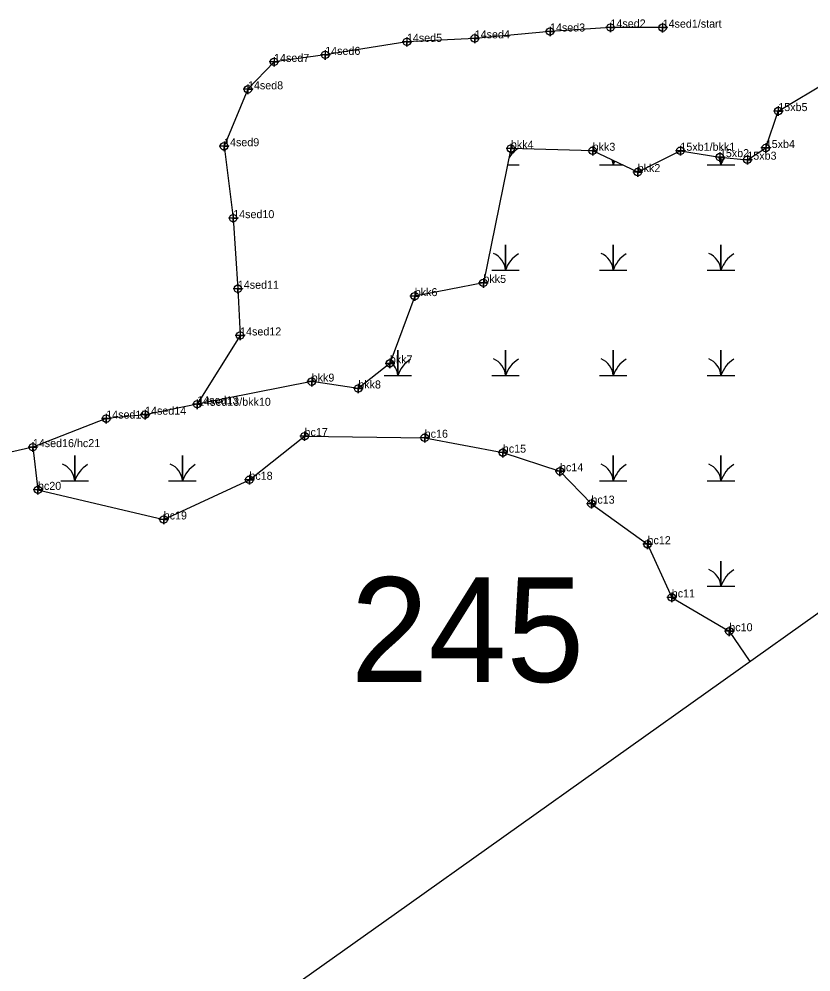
# Model space of a CAD drawing. Extents: x 2071991 to 2268989, y 436479 to 469629.
# Drawn here: x 2266266 to 2266760, y 442376 to 442971 of the extents above; entities that cross this region are included whole.
import ezdxf

# ---------------------------------------------------------------- set-up
doc = ezdxf.new("R2010")
doc.units = 0
for name, color, linetype in [('approx_PSA', 7, 'Continuous'), ('Default', 7, 'Continuous'), ('Exist Environmental Wetland Boundary', 7, 'Continuous'), ('Exist Environmental Wetland Boundary Cogo Comment', 7, 'Continuous'), ('Exist Environmental Wetland Boundary Cogo Point CELL', 7, 'Continuous'), ('Exist Hydro Jurisdictional Stream or Body of Water NEU Mitigable Cogo Comment', 7, 'Continuous'), ('Exist Hydro Jurisdictional Stream or Body of Water NEU Mitigable Cogo Point CELL', 7, 'Continuous'), ('Exist Hydro Jurisdictional Stream or Body of Water NEU NonMitigable', 7, 'Continuous'), ('Exist Hydro Jurisdictional Stream or Body of Water NEU NonMitigable Cogo Comment', 7, 'Continuous'), ('Exist Hydro Jurisdictional Stream or Body of Water NEU NonMitigable Cogo Point CELL', 7, 'Continuous'), ('Exist Hydro Swamp or Marsh', 7, 'Continuous')]:
    doc.layers.add(name, color=color, linetype=linetype)

msp = doc.modelspace()

# ---------------------------------------------------------------- linework, layer by layer
at = {"layer": 'approx_PSA'}
for p, q in [((2267016.7, 442780.01), (2266499.86, 442411.99)), ((2266499.86, 442411.99), (2265822.87, 441931.57))]:
    msp.add_line(p, q, dxfattribs=at)
at = {"layer": 'Exist Environmental Wetland Boundary'}
for points in [[(2266678.5, 442889.05), (2266703.12, 442885.09), (2266720.26, 442883.46), (2266731.75, 442890.78), (2266739.57, 442913.82), (2266772.08, 442933.43)], [(2266678.5, 442889.05), (2266651.85, 442875.73), (2266623.75, 442889.04), (2266572.7, 442890.43), (2266555.58, 442806.57), (2266512.75, 442798.29), (2266497.2, 442756.32), (2266477.5, 442740.62), (2266448.44, 442744.91), (2266377.04, 442730.81)], [(2266274.43, 442704.01), (2266277.64, 442677.33), (2266356.08, 442658.85), (2266409.55, 442683.62), (2266443.97, 442710.87), (2266518.94, 442709.86), (2266567.7, 442700.56), (2266603.36, 442688.91), (2266622.96, 442668.7), (2266657.98, 442643.38), (2266673.11, 442610.19), (2266709.02, 442589.04), (2266721.86, 442570.07)]]:
    msp.add_lwpolyline(points, dxfattribs=at)
at = {"layer": 'Exist Environmental Wetland Boundary Cogo Point CELL'}
for points in [[(2266739.57, 442916.82), (2266739.57, 442910.82), (2266739.57, 442913.82), (2266742.57, 442913.82), (2266736.57, 442913.82)], [(2266572.7, 442893.43), (2266572.7, 442887.43), (2266572.7, 442890.43), (2266575.7, 442890.43), (2266569.7, 442890.43)], [(2266623.75, 442892.04), (2266623.75, 442886.04), (2266623.75, 442889.04), (2266626.75, 442889.04), (2266620.75, 442889.04)], [(2266678.5, 442892.05), (2266678.5, 442886.05), (2266678.5, 442889.05), (2266681.5, 442889.05), (2266675.5, 442889.05)], [(2266731.75, 442893.78), (2266731.75, 442887.78), (2266731.75, 442890.78), (2266734.75, 442890.78), (2266728.75, 442890.78)], [(2266703.12, 442888.09), (2266703.12, 442882.09), (2266703.12, 442885.09), (2266706.12, 442885.09), (2266700.12, 442885.09)], [(2266720.26, 442886.46), (2266720.26, 442880.46), (2266720.26, 442883.46), (2266723.26, 442883.46), (2266717.26, 442883.46)], [(2266651.85, 442878.73), (2266651.85, 442872.73), (2266651.85, 442875.73), (2266654.85, 442875.73), (2266648.85, 442875.73)], [(2266555.58, 442809.57), (2266555.58, 442803.57), (2266555.58, 442806.57), (2266558.58, 442806.57), (2266552.58, 442806.57)], [(2266512.75, 442801.29), (2266512.75, 442795.29), (2266512.75, 442798.29), (2266515.75, 442798.29), (2266509.75, 442798.29)], [(2266497.2, 442759.32), (2266497.2, 442753.32), (2266497.2, 442756.32), (2266500.2, 442756.32), (2266494.2, 442756.32)], [(2266448.44, 442747.91), (2266448.44, 442741.91), (2266448.44, 442744.91), (2266451.44, 442744.91), (2266445.44, 442744.91)], [(2266477.5, 442743.62), (2266477.5, 442737.62), (2266477.5, 442740.62), (2266480.5, 442740.62), (2266474.5, 442740.62)], [(2266443.97, 442713.87), (2266443.97, 442707.87), (2266443.97, 442710.87), (2266446.97, 442710.87), (2266440.97, 442710.87)], [(2266518.94, 442712.86), (2266518.94, 442706.86), (2266518.94, 442709.86), (2266521.94, 442709.86), (2266515.94, 442709.86)], [(2266567.7, 442703.56), (2266567.7, 442697.56), (2266567.7, 442700.56), (2266570.7, 442700.56), (2266564.7, 442700.56)], [(2266603.36, 442691.91), (2266603.36, 442685.91), (2266603.36, 442688.91), (2266606.36, 442688.91), (2266600.36, 442688.91)], [(2266409.55, 442686.62), (2266409.55, 442680.62), (2266409.55, 442683.62), (2266412.55, 442683.62), (2266406.55, 442683.62)], [(2266277.64, 442680.33), (2266277.64, 442674.33), (2266277.64, 442677.33), (2266280.64, 442677.33), (2266274.64, 442677.33)], [(2266622.96, 442671.7), (2266622.96, 442665.7), (2266622.96, 442668.7), (2266625.96, 442668.7), (2266619.96, 442668.7)], [(2266356.08, 442661.85), (2266356.08, 442655.85), (2266356.08, 442658.85), (2266359.08, 442658.85), (2266353.08, 442658.85)], [(2266657.98, 442646.38), (2266657.98, 442640.38), (2266657.98, 442643.38), (2266660.98, 442643.38), (2266654.98, 442643.38)], [(2266673.11, 442613.19), (2266673.11, 442607.19), (2266673.11, 442610.19), (2266676.11, 442610.19), (2266670.11, 442610.19)], [(2266709.02, 442592.04), (2266709.02, 442586.04), (2266709.02, 442589.04), (2266712.02, 442589.04), (2266706.02, 442589.04)]]:
    msp.add_lwpolyline(points, dxfattribs=at)
for centre in [(2266739.57, 442913.82), (2266572.7, 442890.43), (2266623.75, 442889.04), (2266678.5, 442889.05), (2266731.75, 442890.78), (2266703.12, 442885.09), (2266720.26, 442883.46), (2266651.85, 442875.73), (2266555.58, 442806.57), (2266512.75, 442798.29), (2266497.2, 442756.32), (2266448.44, 442744.91), (2266477.5, 442740.62), (2266443.97, 442710.87), (2266518.94, 442709.86), (2266567.7, 442700.56), (2266603.36, 442688.91), (2266409.55, 442683.62), (2266277.64, 442677.33), (2266622.96, 442668.7), (2266356.08, 442658.85), (2266657.98, 442643.38), (2266673.11, 442610.19), (2266709.02, 442589.04)]:
    msp.add_circle(centre, 2.34, dxfattribs=at)
at = {"layer": 'Exist Hydro Jurisdictional Stream or Body of Water NEU Mitigable Cogo Point CELL'}
for points in [[(2266377.04, 442733.81), (2266377.04, 442727.81), (2266377.04, 442730.81), (2266380.04, 442730.81), (2266374.04, 442730.81)], [(2266274.43, 442707.01), (2266274.43, 442701.01), (2266274.43, 442704.01), (2266277.43, 442704.01), (2266271.43, 442704.01)]]:
    msp.add_lwpolyline(points, dxfattribs=at)
for centre in [(2266377.04, 442730.81), (2266274.43, 442704.01)]:
    msp.add_circle(centre, 2.34, dxfattribs=at)
at = {"layer": 'Exist Hydro Jurisdictional Stream or Body of Water NEU NonMitigable'}
msp.add_lwpolyline([(2266667.41, 442965.91), (2266634.85, 442966.02), (2266597.13, 442963.52), (2266550.14, 442959.23), (2266507.85, 442957.06), (2266456.86, 442948.93), (2266424.97, 442944.56), (2266408.67, 442927.41), (2266393.73, 442891.87), (2266399.45, 442846.98), (2266402.33, 442802.9), (2266403.76, 442773.73), (2266377.04, 442730.81), (2266344.45, 442724.27), (2266320.22, 442721.84), (2266274.43, 442704.01), (2266234.92, 442694.97)], dxfattribs=at)
at = {"layer": 'Exist Hydro Jurisdictional Stream or Body of Water NEU NonMitigable Cogo Point CELL'}
for points in [[(2266634.85, 442969.02), (2266634.85, 442963.02), (2266634.85, 442966.02), (2266637.85, 442966.02), (2266631.85, 442966.02)], [(2266667.41, 442968.91), (2266667.41, 442962.91), (2266667.41, 442965.91), (2266670.41, 442965.91), (2266664.41, 442965.91)], [(2266550.14, 442962.23), (2266550.14, 442956.23), (2266550.14, 442959.23), (2266553.14, 442959.23), (2266547.14, 442959.23)], [(2266597.13, 442966.52), (2266597.13, 442960.52), (2266597.13, 442963.52), (2266600.13, 442963.52), (2266594.13, 442963.52)], [(2266507.85, 442960.06), (2266507.85, 442954.06), (2266507.85, 442957.06), (2266510.85, 442957.06), (2266504.85, 442957.06)], [(2266456.86, 442951.93), (2266456.86, 442945.93), (2266456.86, 442948.93), (2266459.86, 442948.93), (2266453.86, 442948.93)], [(2266424.97, 442947.56), (2266424.97, 442941.56), (2266424.97, 442944.56), (2266427.97, 442944.56), (2266421.97, 442944.56)], [(2266408.67, 442930.41), (2266408.67, 442924.41), (2266408.67, 442927.41), (2266411.67, 442927.41), (2266405.67, 442927.41)], [(2266393.73, 442894.87), (2266393.73, 442888.87), (2266393.73, 442891.87), (2266396.73, 442891.87), (2266390.73, 442891.87)], [(2266399.45, 442849.98), (2266399.45, 442843.98), (2266399.45, 442846.98), (2266402.45, 442846.98), (2266396.45, 442846.98)], [(2266402.33, 442805.9), (2266402.33, 442799.9), (2266402.33, 442802.9), (2266405.33, 442802.9), (2266399.33, 442802.9)], [(2266403.76, 442776.73), (2266403.76, 442770.73), (2266403.76, 442773.73), (2266406.76, 442773.73), (2266400.76, 442773.73)], [(2266377.04, 442733.81), (2266377.04, 442727.81), (2266377.04, 442730.81), (2266380.04, 442730.81), (2266374.04, 442730.81)], [(2266320.22, 442724.84), (2266320.22, 442718.84), (2266320.22, 442721.84), (2266323.22, 442721.84), (2266317.22, 442721.84)], [(2266344.45, 442727.27), (2266344.45, 442721.27), (2266344.45, 442724.27), (2266347.45, 442724.27), (2266341.45, 442724.27)], [(2266274.43, 442707.01), (2266274.43, 442701.01), (2266274.43, 442704.01), (2266277.43, 442704.01), (2266271.43, 442704.01)]]:
    msp.add_lwpolyline(points, dxfattribs=at)
for centre in [(2266634.85, 442966.02), (2266667.41, 442965.91), (2266550.14, 442959.23), (2266597.13, 442963.52), (2266507.85, 442957.06), (2266456.86, 442948.93), (2266424.97, 442944.56), (2266408.67, 442927.41), (2266393.73, 442891.87), (2266399.45, 442846.98), (2266402.33, 442802.9), (2266403.76, 442773.73), (2266377.04, 442730.81), (2266320.22, 442721.84), (2266344.45, 442724.27), (2266274.43, 442704.01)]:
    msp.add_circle(centre, 2.34, dxfattribs=at)
at = {"layer": 'Exist Hydro Swamp or Marsh'}
msp.add_line((2266570.62, 442880.25), (2266577.97, 442880.25), dxfattribs=at)
for points in [[(2266695.17, 442880.25), (2266703.77, 442880.25), (2266703.77, 442885.03)], [(2266703.77, 442885.03), (2266703.77, 442880.25), (2266712.37, 442880.25)], [(2266627.97, 442880.25), (2266636.57, 442880.25), (2266636.57, 442882.97)], [(2266636.57, 442882.97), (2266636.57, 442880.25), (2266642.3, 442880.25)], [(2266560.76, 442814.47), (2266569.37, 442814.47), (2266569.37, 442830.25), (2266569.37, 442814.47), (2266577.97, 442814.47)], [(2266627.97, 442814.47), (2266636.57, 442814.47), (2266636.57, 442830.25), (2266636.57, 442814.47), (2266645.17, 442814.47)], [(2266695.17, 442814.47), (2266703.77, 442814.47), (2266703.77, 442830.25), (2266703.77, 442814.47), (2266712.37, 442814.47)], [(2266493.56, 442748.69), (2266502.16, 442748.69), (2266502.16, 442764.47), (2266502.16, 442748.69), (2266510.76, 442748.69)], [(2266560.76, 442748.69), (2266569.37, 442748.69), (2266569.37, 442764.47), (2266569.37, 442748.69), (2266577.97, 442748.69)], [(2266627.97, 442748.69), (2266636.57, 442748.69), (2266636.57, 442764.47), (2266636.57, 442748.69), (2266645.17, 442748.69)], [(2266695.17, 442748.69), (2266703.77, 442748.69), (2266703.77, 442764.47), (2266703.77, 442748.69), (2266712.37, 442748.69)], [(2266291.95, 442682.91), (2266300.55, 442682.91), (2266300.55, 442698.69), (2266300.55, 442682.91), (2266309.15, 442682.91)], [(2266359.15, 442682.91), (2266367.76, 442682.91), (2266367.76, 442698.69), (2266367.76, 442682.91), (2266376.36, 442682.91)], [(2266627.97, 442682.91), (2266636.57, 442682.91), (2266636.57, 442698.69), (2266636.57, 442682.91), (2266645.17, 442682.91)], [(2266695.17, 442682.91), (2266703.77, 442682.91), (2266703.77, 442698.69), (2266703.77, 442682.91), (2266712.37, 442682.91)], [(2266695.17, 442617.13), (2266703.77, 442617.13), (2266703.77, 442632.91), (2266703.77, 442617.13), (2266712.37, 442617.13)]]:
    msp.add_lwpolyline(points, dxfattribs=at)
for centre, radius, start, end in [((2266587.61, 442874.19), 19.22, 123.01685, 146.69336), ((2266691.51, 442879.37), 12.3, 4.14034, 28.41757), ((2266722.01, 442874.19), 19.22, 146.45137, 161.62219), ((2266624.3, 442879.37), 12.3, 4.14034, 18.43258), ((2266654.81, 442874.19), 19.22, 154.28689, 161.62219), ((2266557.1, 442813.59), 12.3, 4.14034, 67.53497), ((2266587.61, 442808.41), 19.22, 122.12745, 161.62219), ((2266624.3, 442813.59), 12.3, 4.14034, 67.53497), ((2266654.81, 442808.41), 19.22, 122.12745, 161.62219), ((2266691.51, 442813.59), 12.3, 4.14034, 67.53497), ((2266722.01, 442808.41), 19.22, 122.12745, 161.62219), ((2266520.4, 442742.63), 19.22, 122.12745, 161.62219), ((2266557.1, 442747.8), 12.3, 4.14034, 67.53497), ((2266587.61, 442742.63), 19.22, 122.12745, 161.62219), ((2266624.3, 442747.8), 12.3, 4.14034, 67.53497), ((2266654.81, 442742.63), 19.22, 122.12745, 161.62219), ((2266691.51, 442747.8), 12.3, 4.14034, 67.53497), ((2266722.01, 442742.63), 19.22, 122.12745, 161.62219), ((2266489.9, 442747.8), 12.3, 4.14034, 51.22363), ((2266288.29, 442682.02), 12.3, 4.14034, 67.53497), ((2266355.49, 442682.02), 12.3, 4.14034, 67.53497), ((2266624.3, 442682.02), 12.3, 4.14034, 67.53497), ((2266691.51, 442682.02), 12.3, 4.14034, 67.53497), ((2266318.79, 442676.85), 19.22, 122.12745, 161.62219), ((2266386, 442676.85), 19.22, 122.12745, 161.62219), ((2266654.81, 442676.85), 19.22, 122.12745, 161.62219), ((2266722.01, 442676.85), 19.22, 122.12745, 161.62219), ((2266691.51, 442616.24), 12.3, 4.14034, 67.53497), ((2266722.01, 442611.07), 19.22, 122.12745, 161.62219)]:
    msp.add_arc(centre, radius, start, end, dxfattribs=at)

# ---------------------------------------------------------------- texts
at = {"layer": 'Default'}
msp.add_text('245', height=65.34, dxfattribs=at).set_placement((2266472.73, 442557.41))
at = {"layer": 'Exist Environmental Wetland Boundary Cogo Comment'}
for s, p in [('15xb5', (2266739.57, 442913.82)), ('bkk4', (2266572.7, 442890.43)), ('15xb4', (2266731.75, 442890.78)), ('bkk3', (2266623.75, 442889.04)), ('15xb1/bkk1', (2266678.5, 442889.05)), ('15xb2', (2266703.12, 442885.09)), ('15xb3', (2266720.26, 442883.46)), ('bkk2', (2266651.85, 442875.73)), ('bkk5', (2266555.58, 442806.57)), ('bkk6', (2266512.75, 442798.29)), ('bkk7', (2266497.2, 442756.32)), ('bkk9', (2266448.44, 442744.91)), ('bkk8', (2266477.5, 442740.62)), ('hc17', (2266443.97, 442710.87)), ('hc16', (2266518.94, 442709.86)), ('hc15', (2266567.7, 442700.56)), ('hc14', (2266603.36, 442688.91)), ('hc18', (2266409.55, 442683.62)), ('hc20', (2266277.64, 442677.33)), ('hc13', (2266622.96, 442668.7)), ('hc19', (2266356.08, 442658.85)), ('hc12', (2266657.98, 442643.38)), ('hc11', (2266673.11, 442610.19)), ('hc10', (2266709.02, 442589.04))]:
    msp.add_text(s, height=5, dxfattribs=at).set_placement(p)
at = {"layer": 'Exist Hydro Jurisdictional Stream or Body of Water NEU Mitigable Cogo Comment'}
for s, p in [('14sed13', (2266377.04, 442730.81)), ('14sed16', (2266274.43, 442704.01))]:
    msp.add_text(s, height=5, dxfattribs=at).set_placement(p)
at = {"layer": 'Exist Hydro Jurisdictional Stream or Body of Water NEU NonMitigable Cogo Comment'}
for s, p in [('14sed3', (2266597.13, 442963.52)), ('14sed2', (2266634.85, 442966.02)), ('14sed1/start', (2266667.41, 442965.91)), ('14sed5', (2266507.85, 442957.06)), ('14sed4', (2266550.14, 442959.23)), ('14sed7', (2266424.97, 442944.56)), ('14sed6', (2266456.86, 442948.93)), ('14sed8', (2266408.67, 442927.41)), ('14sed9', (2266393.73, 442891.87)), ('14sed10', (2266399.45, 442846.98)), ('14sed11', (2266402.33, 442802.9)), ('14sed12', (2266403.76, 442773.73)), ('14sed13/bkk10', (2266377.54, 442729.81)), ('14sed14', (2266344.45, 442724.27)), ('14sed15', (2266320.22, 442721.84)), ('14sed16/hc21', (2266274.43, 442704.01))]:
    msp.add_text(s, height=5, dxfattribs=at).set_placement(p)

doc.saveas('drawing.dxf')
